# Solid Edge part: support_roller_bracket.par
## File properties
Title: Support roller bracket
Author: Deepak Maini
Template: Normal.par
Last saved by: CADCIM
Revision: 16
Application: Solid Edge
Accuracy: 0.99
Material: aluminum
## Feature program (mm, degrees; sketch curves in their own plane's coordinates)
sketch for "unnamed Protrusion 1" #1 plane through (0, 0, 0) normal (0, -1, 0) x-axis (1, 0, 0)
  circle centre (0, -138.9237) radius 3.81
sketch for "unnamed Protrusion 1" #2 plane through (0, 0, 0) normal (0, -1, 0) x-axis (1, 0, 0)
  line (143.637, -99.9249) -> (-143.637, -99.9249)
  line (-143.637, -99.9249) -> (-143.637, -115.1647)
  line (-143.637, -115.1647) -> (-61.0846, -156.7704)
  line (-61.0846, -156.7704) -> (-61.0846, -162.9363)
  line (-61.0846, -162.9363) -> (61.0846, -162.9363)
  line (61.0846, -156.7704) -> (61.0846, -162.9363)
  line (143.637, -115.1647) -> (61.0846, -156.7704)
  line (143.637, -99.9249) -> (143.637, -115.1647)
  dimension (linear) = 143.637
extrude "unnamed Protrusion 1" add finite 101.6 symmetric
fillet "Round_1" radius 31.75
fillet "Round_2" radius 6.35
sketch for "unnamed Protrusion 2" plane through (0, 0, 67.2512) normal (1, 0, 0) x-axis (0, 1, 0)
  arc centre (-23.4135, -61.792) radius 19.05 from (-23.4135, -42.742) to (-42.405, -60.3002) ccw
  line (-50.8, -167.1761) -> (-42.405, -60.3002)
  line (-50.8, -167.1761) -> (50.8, -167.1761)
  line (45.7777, -60.8928) -> (50.8, -167.1761)
  arc centre (26.749, -61.792) radius 19.05 from (26.749, -42.742) to (45.7777, -60.8928) cw
  line (19.05, -42.742) -> (26.749, -42.742)
  line (19.05, -64.967) -> (19.05, -42.742)
  arc centre (0, -64.967) radius 19.05 from (-19.05, -64.967) to (19.05, -64.967) ccw
  line (-19.05, -42.742) -> (-19.05, -64.967)
  line (-23.4135, -42.742) -> (-19.05, -42.742)
extrude "unnamed Protrusion 2" add to key point symmetric
sketch for "ExtrudedCutout_1" plane through (0, 0, 0) normal (0, -1, 0) x-axis (1, 0, 0)
  line (-128.3193, 24.5092) -> (125.6319, 24.5092)
  line (125.6319, 24.5092) -> (125.6319, -99.9249)
  line (125.6319, -99.9249) -> (-128.3193, -99.9249)
  line (-128.3193, -99.9249) -> (-128.3193, 24.5092)
extrude "ExtrudedCutout_1" cut finite 203.2 symmetric
chamfer "Chamfer_1" setback 5.08
rib "Rib_1"  Thickness = 25.4 mm
mirror "unnamed Mirror 1" of "Rib_1" about plane through (0, 0, 0) normal (1, 0, 0)
rib "unnamed Rib 1"
sketch for "Hole_1" plane through (0.1259, 0, -162.9363) normal (0, 0, -1) x-axis (-1, 0, 0)
  hole centre (0.1259, 0) bore radius 25.4
hole "Hole_1" diameter 50.8 through
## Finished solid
Body 1: solid body, 55 faces, 142 edges, 86 vertices.
  Faces by surface: plane 38, cylinder 17
  Edges by curve: line 106, circle 34, intersection 2
Bounding box of the edges (mm): 379.121 x 101.600 x 187.446, from (-189.5605, -50.8, -162.9363) to (189.5605, 50.8, 24.5092).
Cylindrical faces by radius (mm): R3.81 x2, R6.35 x2, R19.05 x6, R25.4 x1, R31.75 x4, R55.372 x2
Planar faces by outward normal: +x 4, +y 5, +z 5, -x 4, -y 5, -z 1, oblique 14
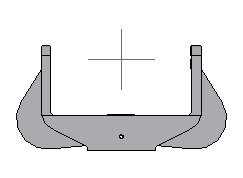
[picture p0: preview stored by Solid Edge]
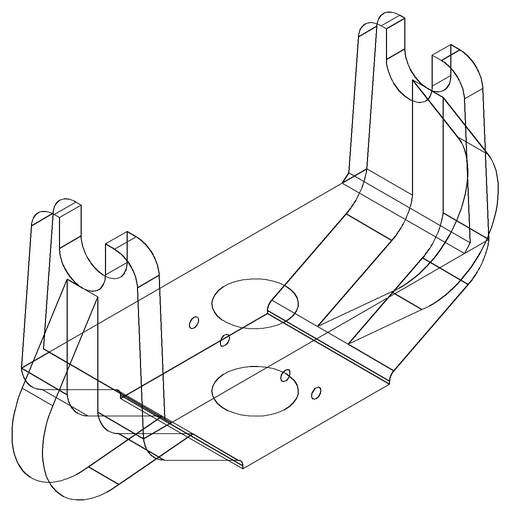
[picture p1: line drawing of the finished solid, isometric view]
